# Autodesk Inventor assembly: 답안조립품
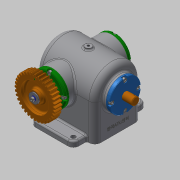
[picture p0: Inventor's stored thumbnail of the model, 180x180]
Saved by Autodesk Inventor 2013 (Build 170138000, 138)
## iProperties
Created: 2019-05
Part Number: 답안조립품
Document SubType Name: Assembly
Designer: Administrator
Author: Administrator
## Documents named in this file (16)
- C:\Users\Administrator\Desktop\390504V1034\답안조립품.iam
- C:\Users\Administrator\Desktop\390504V1034\본체.ipt
- C:\Users\Administrator\Desktop\390504V1034\가이드부시.ipt
- C:\Users\Administrator\Desktop\390504V1034\베어링 6203.ipt
- C:\Users\Administrator\Desktop\390504V1034\볼트 M4x8.ipt
- C:\Users\Administrator\Desktop\390504V1034\볼트 M4x10.ipt
- C:\Users\Administrator\Desktop\390504V1034\스퍼기어.ipt
- C:\Users\Administrator\Desktop\390504V1034\스프링와셔.ipt
- C:\Users\Administrator\Desktop\390504V1034\슬라이더.ipt
- C:\Users\Administrator\Desktop\390504V1034\오일 실 17 32 8.ipt
- C:\Users\Administrator\Desktop\390504V1034\커버 A.ipt
- C:\Users\Administrator\Desktop\390504V1034\커버 B.ipt
- C:\Users\Administrator\Desktop\390504V1034\키 4x4x14.ipt
- C:\Users\Administrator\Desktop\390504V1034\편심축.ipt
- C:\Users\Administrator\Desktop\390504V1034\평와셔.ipt
- C:\Users\Administrator\Desktop\390504V1034\가변스프링.ipt
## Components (2 placed, 2 different names)
1. 가이드부시:1
2. 가변스프링:1
